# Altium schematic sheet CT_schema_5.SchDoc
size 479 x 328 mm
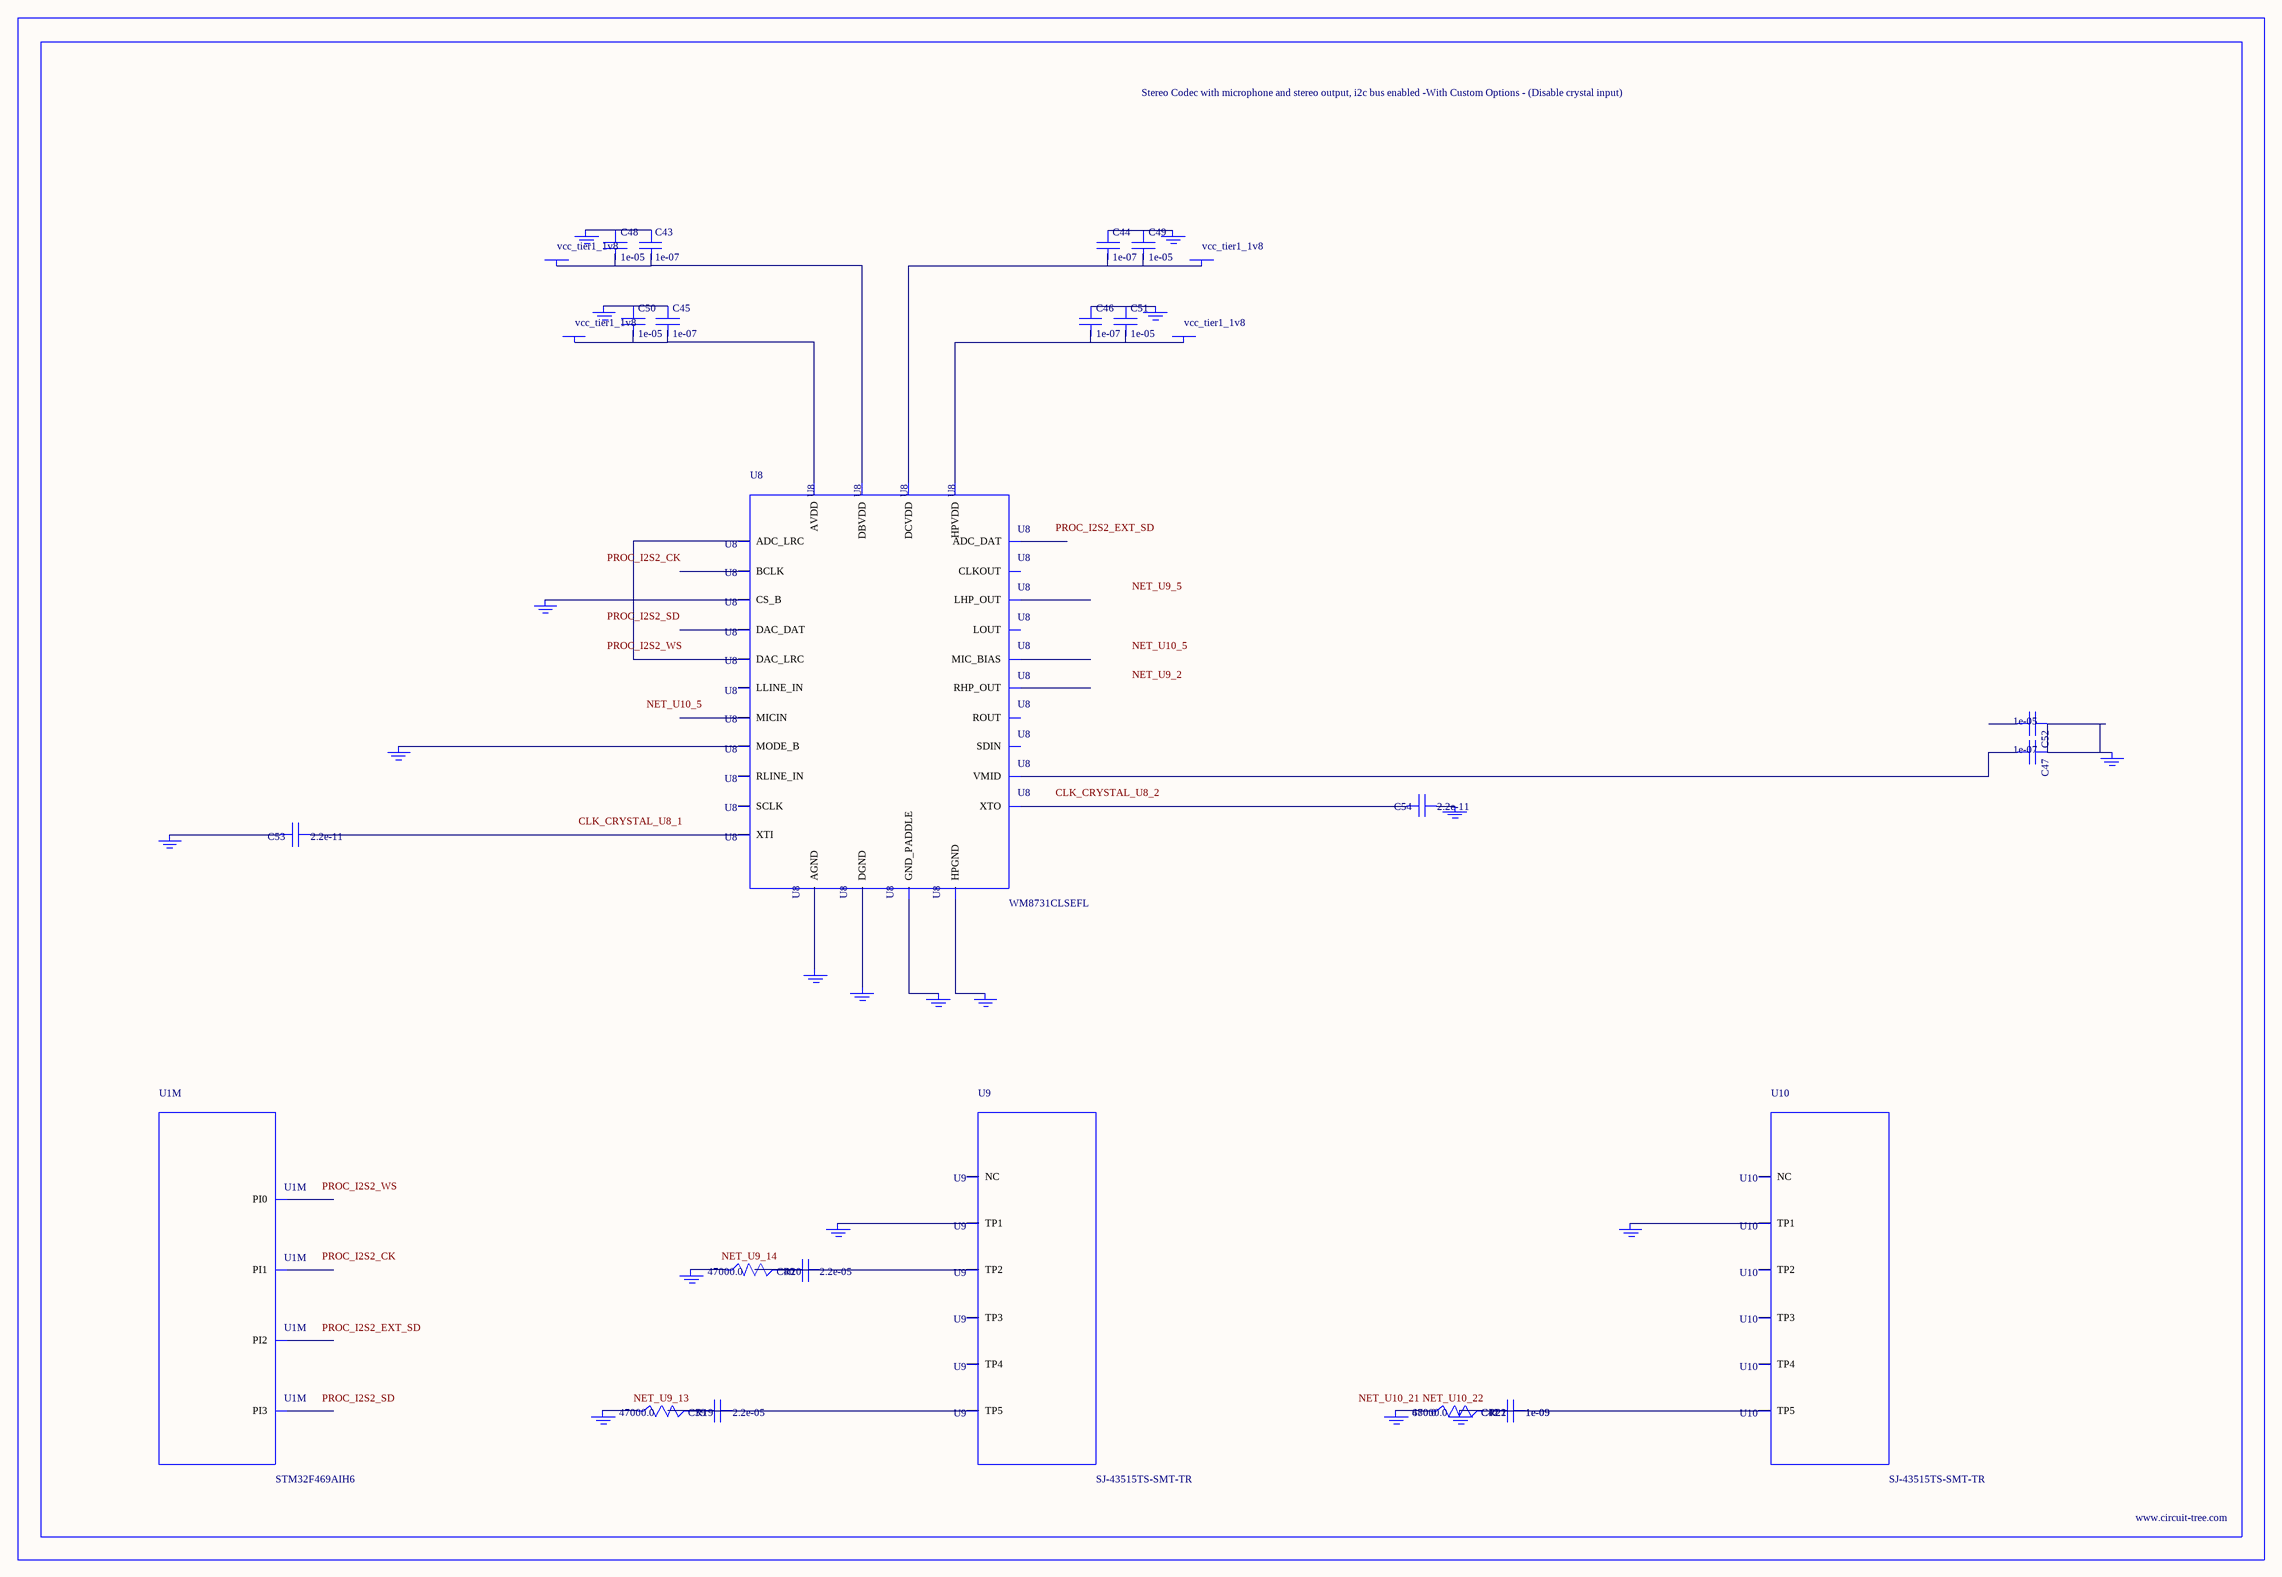
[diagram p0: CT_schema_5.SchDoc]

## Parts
BORDER4  (no value)
C39  2.2e-05  [C1210]
C40  2.2e-05  [C1210]
C41  1e-09  [C0402]
C42  1e-09  [C0402]
C43  1e-07  [C0402]
C44  1e-07  [C0402]
C45  1e-07  [C0402]
C46  1e-07  [C0402]
C47  1e-07  [C0402]
C48  1e-05  [C0805]
C49  1e-05  [C0805]
C50  1e-05  [C0805]
C51  1e-05  [C0805]
C52  1e-05  [C0805]
C53  2.2e-11  [C0402]
C54  2.2e-11  [C0402]
GND_INSTANCE_4_0  (no value)
GND_INSTANCE_4_1  (no value)
GND_INSTANCE_4_2  (no value)
GND_INSTANCE_4_3  (no value)
GND_INSTANCE_4_4  (no value)
GND_INSTANCE_4_5  (no value)
GND_INSTANCE_4_6  (no value)
GND_INSTANCE_4_7  (no value)
GND_INSTANCE_4_8  (no value)
GND_INSTANCE_4_9  (no value)
GND_INSTANCE_4_10  (no value)
GND_INSTANCE_4_11  (no value)
GND_INSTANCE_4_12  (no value)
GND_INSTANCE_4_13  (no value)
GND_INSTANCE_4_14  (no value)
GND_INSTANCE_4_15  (no value)
GND_INSTANCE_4_16  (no value)
GND_INSTANCE_4_17  (no value)
GND_INSTANCE_4_18  (no value)
POWER_INSTANCE_4_0  vcc_tier1_1v8
POWER_INSTANCE_4_1  vcc_tier1_1v8
POWER_INSTANCE_4_2  vcc_tier1_1v8
POWER_INSTANCE_4_3  vcc_tier1_1v8
R19  47000.0  [R0603]
R20  47000.0  [R0603]
R21  47000.0  [R0603]
R22  680.0  [R0603]
U1  STM32F469AIH6  [UFBGA169]  (part M of 13)
U8  WM8731CLSEFL  [QFN-28]
U9  SJ-43515TS-SMT-TR  [SJ-43515TS-SMT-TR]
U10  SJ-43515TS-SMT-TR  [SJ-43515TS-SMT-TR]

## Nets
NetC39_1: C39.1 C39.2 R19.2 U9.5(TP5)
NetC40_1: C40.1 C40.2 R20.2 U9.2(TP2)
NetC41_1: C41.1 C41.2 C42.1 C42.2 GND_INSTANCE_4_18.0(GND) R21.2 R22.2 U10.5(TP5)
NetC43_1: C43.1 C48.1 GND_INSTANCE_4_3.0(GND)
NetC43_2: C43.2 C48.2 POWER_INSTANCE_4_1.0(PWR) U8.5(DBVDD)
NetC44_1: C44.1 C49.1 GND_INSTANCE_4_2.0(GND)
NetC44_2: C44.2 C49.2 POWER_INSTANCE_4_0.0(PWR) U8.3(DCVDD)
NetC45_1: C45.1 C50.1 GND_INSTANCE_4_6.0(GND)
NetC45_2: C45.2 C50.2 POWER_INSTANCE_4_3.0(PWR) U8.18(AVDD)
NetC46_1: C46.1 C51.1 GND_INSTANCE_4_4.0(GND)
NetC46_2: C46.2 C51.2 POWER_INSTANCE_4_2.0(PWR) U8.12(HPVDD)
NetC47_1: C47.1 C52.1 GND_INSTANCE_4_7.0(GND)
NetC47_2: C47.2 U8.20(VMID)
NetC53_1: C53.1 U8.1(XTI)
NetC53_2: C53.2 GND_INSTANCE_4_0.0(GND)
NetC54_1: C54.1 GND_INSTANCE_4_1.0(GND)
NetC54_2: C54.2 U8.2(XTO)
NetGND_INSTANCE_4_5_0: GND_INSTANCE_4_5.0(GND) U8.15(HPGND)
NetGND_INSTANCE_4_8_0: GND_INSTANCE_4_8.0(GND) U8.25(MODE_B)
NetGND_INSTANCE_4_9_0: GND_INSTANCE_4_9.0(GND) U8.26(CS_B)
NetGND_INSTANCE_4_10_0: GND_INSTANCE_4_10.0(GND) U8.29(GND_PADDLE)
NetGND_INSTANCE_4_11_0: GND_INSTANCE_4_11.0(GND) U8.4(DGND)
NetGND_INSTANCE_4_12_0: GND_INSTANCE_4_12.0(GND) U8.19(AGND)
NetGND_INSTANCE_4_13_0: GND_INSTANCE_4_13.0(GND) U9.1(TP1)
NetGND_INSTANCE_4_14_0: GND_INSTANCE_4_14.0(GND) R20.1
NetGND_INSTANCE_4_15_0: GND_INSTANCE_4_15.0(GND) R19.1
NetGND_INSTANCE_4_16_0: GND_INSTANCE_4_16.0(GND) U10.1(TP1)
NetGND_INSTANCE_4_17_0: GND_INSTANCE_4_17.0(GND) R21.1 R22.1
NetU8_9: U8.9(DAC_LRC) U8.11(ADC_LRC)

Not connected (* = marked no-connect by the designer): C52 2; U1 B10(PI3) B12(PI2) B13(PI0) C11(PI1); U8 6(CLKOUT) 7(BCLK) 8(DAC_DAT) 10(ADC_DAT) 13(LHP_OUT) 14(RHP_OUT) 16(LOUT) 17(ROUT) 21(MIC_BIAS) 22(MICIN) 23(RLINE_IN) 24(LLINE_IN) 27(SDIN) 28(SCLK); U9 3(TP3) 4(TP4) 6(NC); U10 2(TP2) 3(TP3) 4(TP4) 6(NC)

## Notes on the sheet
- Labels drawn without touching a wire or pin: CLK_CRYSTAL_U8_1, CLK_CRYSTAL_U8_2, NET_U9_2, NET_U9_5, NET_U9_13, NET_U9_14, NET_U10_5, NET_U10_21, NET_U10_22, PROC_I2S2_CK, PROC_I2S2_EXT_SD, PROC_I2S2_SD, PROC_I2S2_WS

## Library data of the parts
BORDER4 = BORDER_PAGE4
C39 C40 = C1210C224K5RACTU
C41 C42 = C0402C102K3RAC
C43-C47 = C0402C104K3RACTU
C48-C52 = C0805C106K8RACTU
C53 C54 = C0402C220K3RAC
GND_INSTANCE_4_0-GND_INSTANCE_4_18 = GND
POWER_INSTANCE_4_0-POWER_INSTANCE_4_3 = PWR
R19-R21 = RC0603JR-0747KL
R22 = RC0603JR-07680RL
